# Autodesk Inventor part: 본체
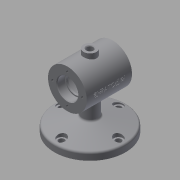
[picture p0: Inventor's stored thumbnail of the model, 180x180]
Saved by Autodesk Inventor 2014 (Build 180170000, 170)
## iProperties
Created: 2018-12
Part Number: 본체
Material: Generic
Document SubType Name: Modeling
Designer: kh
Density: 1 g/cm^3
Appearance: Default
Author: kh
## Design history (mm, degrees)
sketch "Sketch1"
  geometry: C1 r 55 at (0, 0); 1 further point
  constraints: 1 centre point, 1 coincident
  dimensions: "d0" = 110 diameter of C1
extrude "Extrusion1" new body sketch "Sketch1" distance "d1" = 11; taper "d2" = 0 deg
workplane "Work Plane1"
workplane "Work Plane2"
workplane "Work Plane3"
workplane "Work Plane5"
workplane "Work Plane6"
workplane "Work Plane7"
sketch "Sketch14"
  geometry: L1 (-47.043, 75)-(44.509, 75); L2 (-55, 0)-(55, 0) reference; L3 (-35, 105)-(35, 105); L4 (35, 105)-(35, 75); L5 (-35, 75)-(-35, 105); L6 (0, 0)-(0, 125.923); L7 (-35, 75)-(-23, 75); L8 (-23, 75)-(-23, 90.7); L9 (-23.3, 91)-(-35, 91); L10 (-35, 91)-(-35, 75); L11 (-23, 75)-(-20, 75); L12 (-20, 75)-(-20, 89); L13 (-20, 89)-(-23, 89); L14 (-23, 89)-(-23, 75); L15 (-20, 75)-(20, 75); L16 (20, 75)-(20, 97); L17 (17, 100)-(-17, 100); L18 (-20, 97)-(-20, 75); L19 (20, 75)-(23, 75); L20 (23, 75)-(23, 89); L21 (23, 89)-(20, 89); L22 (20, 89)-(20, 75); L23 (23, 75)-(35, 75); L24 (35, 75)-(35, 91); L25 (35, 91)-(23.3, 91); L26 (23, 90.7)-(23, 75); A1 r 3 centre (-17, 97) between (-17, 100) and (-20, 97); A2 r 3 centre (17, 97) between (20, 97) and (17, 100); A3 r 0.3 centre (-23.3, 90.7) between (-23, 90.7) and (-23.3, 91); A4 r 0.3 centre (23.3, 90.7) between (23.3, 91) and (23, 90.7)
  constraints: 50 end point, 12 parallel, 8 point on circle, 8 tangent, 7 horizontal, 6 perpendicular, 4 centre point, 3 point on line, 2 equal radius, 2 other
  dimensions: "d83" = 75 distance between parallel lines of L2 L1; "d84" = 70 distance between parallel lines of L4 L5; "d85" = 60 diameter of L3 L1; "d86" = 32 diameter of L9 L1; "d87" = 28 diameter of L13 L1; "d88" = 50 diameter of L17 L1; "d89" = 28 diameter of L21 L1; "d90" = 32 diameter of L25 L1; "d91" = 12 distance between parallel lines of L4 L20; "d92" = 12 distance between parallel lines of L5 L14; "d93" = 40 distance between parallel lines of L22 L18; "d94" = 3 radius of A1; "d95" = 0.3 radius of A3
revolve "Revolution3" sketch "Sketch14" stored, may be unused: angle "d96" = 90 deg
sketch "Sketch15"
  geometry: C1 r 12 at (0, 0); 1 further point
  constraints: 1 centre point, 1 coincident
  dimensions: "d97" = 24 diameter of C1
extrude "Extrusion5" join sketch "Sketch15" stored distance "d98" = 10; taper "d99" = 0 deg
sketch "Sketch16"
  geometry: L1 (55, 11)-(-55, 11) reference; L2 (-55, 0)-(-55, 11) reference; L3 (-12, 11)-(-12, 45) reference; L4 (-55, 11)-(-6.532, 23.987); L5 (-6.532, 23.987)-(-6.532, 11); L6 (-55, 11)-(-6.532, 11); L7 (0, 0)-(0, 37.906)
  constraints: 8 end point, 2 perpendicular, 1 collinear, 1 point on line
  dimensions: "d100" = 75 deg angle of L2 L4; "d101" = 12.98704 distance of L4.end L5.end
revolve "Revolution4" sketch "Sketch16" stored, may be unused: angle "d102" = 90 deg
sketch "Sketch17" dims "d103" = 88
  geometry: L1 (0, 0)-(0, 44); 2 further points
  constraints: 2 coincident, 2 end point, 1 vertical, 1 vertical alignment, 2 other
hole "Hole4" sketch "Sketch17" at (0, 44) diameter "d104" = 9; stored, may be unused: countersink angle "d108" = 90 deg, drill point angle "d110" = 0 deg; dims "d105" = 6, "d106" = 4, "d107" = 2, "d109" = 10
sketch "Sketch18"
  geometry: C1 r 4.5 at (0, 0) reference; C2 r 7 at (0, 0); 1 further point
  constraints: 1 centre point, 1 coincident
  dimensions: "d111" = 14 diameter of C2
extrude "Extrusion6" cut sketch "Sketch18" distance "d112" = 10; taper "d113" = 0 deg
pattern_circular "Circular Pattern3" dims angle "d115" = 360 deg
sketch "Sketch19" dims "d117" = 46
  geometry: L1 (0, 0)-(0, 23); C1 r 14 at (0, 0) reference; 2 further points
  constraints: 2 coincident, 2 end point, 1 vertical, 1 vertical alignment, 2 other
hole "Hole5" sketch "Sketch19" at (0, 23) diameter "d118" = 3.459; stored, may be unused: countersink angle "d122" = 90 deg, drill point angle "d124" = 118 deg; dims "d119" = 8, "d120" = 4, "d121" = 2, "d123" = 10
pattern_circular "Circular Pattern4" dims angle "d126" = 360 deg
workplane "Work Plane8"
mirror "Mirror2"
chamfer "Chamfer2" distance "d129" = 1; stored, may be unused: second distance "d130" = 2, angle "d131" = 45 deg
workplane "Work Plane9"
sketch "Sketch20"
  geometry: C1 r 10 at (0, 0); 1 further point
  constraints: 1 centre point, 1 coincident
  dimensions: "d133" = 20 diameter of C1
extrude "Extrusion7" join sketch "Sketch20" stored distance "d134" = 10; taper "d135" = 0 deg
hole "Hole6" diameter "d138" = 10; stored, may be unused: countersink angle "d142" = 90 deg, drill point angle "d144" = 118 deg; dims "d136" = 10, "d137" = 10, "d139" = 8, "d140" = 4, "d141" = 2, "d143" = 25
chamfer "Chamfer3" distance "d145" = 1; stored, may be unused: second distance "d146" = 2, angle "d147" = 45 deg
fillet "Fillet4" dims "d148" = 3
workplane "Work Plane10"
sketch "Sketch21" dims "d96" = 90 deg, "d136" = 10, "d137" = 10
  geometry: L1 (-35, 105)-(35, 105) reference; L2 (-35, 45)-(-35, 105) reference; L3 (-24.887, 78.602)-(24.887, 78.602); L4 (24.887, 78.602)-(24.887, 71.398); L5 (24.887, 71.398)-(-24.887, 71.398); L6 (-24.887, 71.398)-(-24.887, 78.602); L7 (0, 105)-(0, 0); L8 (-35, 75)-(0, 75); L9 (24.887, 71.398)-(-24.887, 78.602); 1 further point
  constraints: 6 end point, 3 midpoint, 1 coincident, 1 parallel, 1 perpendicular, 1 point on line, 2 other
  dimensions: "d150" = 30 distance between parallel lines of L1 L8
emboss "Emboss2" sketch "Sketch21" dims "d1" = 11, "d2" = 0, "d151" = 0.5, "d152" = 0
body "Solid1"
node "Projected Loop5"
other parameters: "d3" = 0, "d13" = 75, "d40" = 112, "d74" = 71.5, "d77" = 0, "d82" = 0, "d128" = 0, "d132" = 112, "d149" = 58.75
